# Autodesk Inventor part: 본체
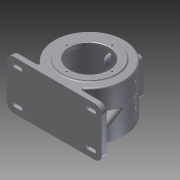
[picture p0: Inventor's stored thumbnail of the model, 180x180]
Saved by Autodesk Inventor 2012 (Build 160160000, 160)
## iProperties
Created: 2015-06
Part Number: 본체
Material: Default
Document SubType Name: Modeling
Designer: user
Density: 1 g/cm^3
Author: user
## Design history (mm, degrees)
sketch "스케치1"
  geometry: L1 (-115, 59)-(115, 59); L2 (115, 59)-(115, -59); L3 (115, -59)-(-115, -59); L4 (-115, -59)-(-115, 59); 3 further points
  constraints: 8 end point, 2 midpoint, 2 parallel, 1 horizontal, 1 horizontal alignment, 1 perpendicular, 1 vertical alignment
  dimensions: "d0" = 230 distance of L1.start L1.end; "d1" = 118 distance of L1.end L2.end
extrude "돌출1" new body sketch "스케치1" distance "d2" = 14; taper "d3" = 0 deg
node "작업 평면1"
sketch "스케치2"
  geometry: C1 r 65 at (115, 85); 1 further point
  constraints: 1 centre point, 1 vertical alignment
  dimensions: "d5" = 130 diameter of C1; "d6" = 85 distance of point (115, 0) C1.centre
extrude "돌출2" join sketch "스케치2" distance "d7" = 13; taper "d8" = 0 deg
sketch "스케치3"
  geometry: C1 r 65 at (0, 0) reference; C2 r 85 at (0, 0); 1 further point
  constraints: 1 centre point, 1 coincident
  dimensions: "d9" = 170 diameter of C2
extrude "돌출3" join sketch "스케치3" distance "d10" = 118; taper "d11" = 0 deg
sketch "스케치4"
  geometry: C1 r 65 at (115, 85); A1 r 85 centre (115, 85) between (161.733, 14) and (68.267, 14) reference; 1 further point
  constraints: 1 centre point, 1 coincident
  dimensions: "d12" = 130 diameter of C1
extrude "돌출4" join sketch "스케치4" distance "d13" = 3; taper "d14" = 0 deg
sketch "스케치5"
  geometry: C1 r 65 at (0, 0) reference; C2 r 47.5 at (0, 0); 1 further point
  constraints: 1 centre point, 1 coincident
  dimensions: "d15" = 95 diameter of C2
extrude "돌출5" cut sketch "스케치5" distance "d16" = 11; taper "d17" = 0 deg
sketch "스케치7"
  geometry: L1 (132.5, 51)-(37.5, 51) reference; L2 (85, 51)-(85, -72); L3 (150, -72)-(20, -72) reference; L4 (14, 59)-(14, -59) reference; L5 (85, 51)-(162, 51); L6 (162, 51)-(162, -51); L7 (162, -51)-(116, -51); L8 (116, -51)-(114.368, -47.5); L9 (114.368, -47.5)-(85, -47.5); 1 further point
  constraints: 12 end point, 3 perpendicular, 2 midpoint, 2 point on line
  dimensions: "d19" = 154 diameter of L5.end L2; "d20" = 102 distance of L5.end L6.end; "d21" = 62 diameter of L7.end L2; "d22" = 3.5 vertical distance of L7.end L8.end; "d23" = 115 deg angle of L7 L8
revolve "회전1" sketch "스케치7" stored, may be unused: angle "d24" = 90 deg
sketch "스케치8"
  geometry: C1 r 29.368 at (0, 0) reference; C2 r 23.5 at (0, 0); 1 further point
  constraints: 1 centre point, 1 coincident
  dimensions: "d25" = 47 diameter of C2
extrude "돌출6" cut sketch "스케치8" distance "d26" = 14; taper "d27" = 0 deg
sketch "스케치9"
  geometry: C1 r 23.5 at (0, 0) reference; C2 r 15 at (0, 0); 1 further point
  constraints: 1 centre point, 1 coincident
  dimensions: "d28" = 30 diameter of C2
extrude "돌출7" cut sketch "스케치9" distance "d29" = 3; taper "d30" = 0 deg
sketch "스케치11"
  geometry: L1 (-115, 59)-(115, 59) reference; L2 (0, 59)-(0, -59); L3 (-115, -59)-(-115, 59) reference; L4 (-115, 0)-(115, 0); L5 (115, 59)-(115, -59) reference; L6 (-97, 50)-(-81, 50); L7 (-97, 32)-(-81, 32); L8 (-97, -50)-(-81, -50); L9 (-97, -32)-(-81, -32); A1 r 9 centre (-97, 41) between (-97, 50) and (-97, 32); A2 r 9 centre (-81, 41) between (-81, 32) and (-81, 50); A3 r 9 centre (-97, -41) between (-97, -32) and (-97, -50); A4 r 9 centre (-81, -41) between (-81, -50) and (-81, -32); 3 further points
  constraints: 12 end point, 8 point on circle, 6 symmetric about line, 5 midpoint, 4 centre point, 4 coincident, 3 perpendicular, 3 tangent, 1 parallel, 2 other
  dimensions: "d40" = 18 diameter of A1; "d41" = 18 diameter of A2; "d42" = 16 distance of A2.centre A1.centre; "d43" = 194 diameter of A1.centre L2; "d44" = 82 diameter of A1.centre L4
extrude "돌출9" join sketch "스케치11" distance "d45" = 3; taper "d46" = 0 deg
sketch "스케치13"
  geometry: L1 (-97, 45)-(-81, 45); L2 (-97, 37)-(-81, 37); A1 r 9 centre (-97, 41) between (-97, 50) and (-97, 32) reference; A2 r 9 centre (-81, 41) between (-81, 32) and (-81, 50) reference; A3 r 4 centre (-97, 41) between (-97, 45) and (-97, 37); A4 r 4 centre (-81, 41) between (-81, 37) and (-81, 45); 1 further point
  constraints: 4 end point, 4 point on circle, 3 tangent, 2 centre point, 2 coincident, 1 parallel
  dimensions: "d47" = 8 diameter of A3; "d48" = 8 diameter of A4
extrude "돌출10" cut sketch "스케치13" stored distance "d49" = 3; taper "d50" = 0 deg
sketch "스케치14"
  geometry: L1 (-115, 14)-(-46.733, 14) reference; L2 (-109, 14)-(-84.87, 80.297); L3 (-109, 14)-(-46.733, 14); A1 r 85 centre (0, 85) between (46.733, 14) and (-46.733, 14) reference; 1 further point
  constraints: 4 end point, 1 collinear, 1 point on circle, 1 point on line
  dimensions: "d52" = 110 deg angle of L1 L2; "d53" = 6 distance of L2.start L1.start
extrude "돌출11" join sketch "스케치14" stored distance "d54" = 15; taper "d55" = 0 deg
node "작업 평면2"
sketch "스케치15"
  geometry: L1 (-42.5, 42.5)-(42.5, 42.5); L2 (42.5, 42.5)-(42.5, -42.5); L3 (42.5, -42.5)-(-42.5, -42.5); L4 (-42.5, -42.5)-(-42.5, 42.5); 3 further points
  constraints: 8 end point, 2 midpoint, 2 parallel, 2 perpendicular, 1 horizontal, 1 horizontal alignment, 1 vertical alignment
  dimensions: "d57" = 85 distance of L1.start L1.end
extrude "돌출12" join sketch "스케치15" stored distance "d58" = 15; taper "d59" = 0 deg
sketch "스케치16"
  geometry: C1 r 35 at (0, 0); 1 further point
  constraints: 1 centre point, 1 coincident
  dimensions: "d60" = 70 diameter of C1
extrude "돌출13" cut sketch "스케치16" stored distance "d61" = 15; taper "d62" = 0 deg
sketch "스케치18"
  geometry: C1 r 47.5 at (0, 0) reference; 2 further points
  constraints: 1 vertical alignment
  dimensions: "d64" = 55 distance of C1.centre point (0, 55)
hole "구멍1" sketch "스케치18" at (0, 55) diameter "d65" = 3.242; stored, may be unused: countersink angle "d69" = 90 deg, drill point angle "d71" = 0 deg; dims "d66" = 11, "d67" = 4, "d68" = 2, "d70" = 8
sketch "스케치19"
  geometry: L1 (42.5, -42.5)-(-42.5, -42.5) reference; L2 (42.5, 42.5)-(42.5, -42.5) reference; L3 (-42.5, 42.5)-(42.5, 42.5) reference; L4 (-42.5, -42.5)-(-42.5, 42.5) reference; L5 (-42.5, 0)-(42.5, 0); L6 (0, 42.5)-(0, -42.5); 1 further point
  constraints: 4 end point, 4 midpoint
  dimensions: "d75" = 71 diameter of point (-35.5, 35.5) L6; "d76" = 71 diameter of point (-35.5, 35.5) L5
hole "구멍2" sketch "스케치19" at (-35.5, 35.5) diameter "d77" = 3.242; stored, may be unused: countersink angle "d81" = 90 deg, drill point angle "d83" = 118 deg; dims "d78" = 10, "d79" = 4, "d80" = 2, "d82" = 13
fillet "모깎기2" dims "d85" = 7.5
fillet "모깎기3" dims "d86" = 7
fillet "모깎기4" dims "d87" = 3
fillet "모깎기5" dims "d88" = 3
fillet "모깎기7" dims "d90" = 18
fillet "모깎기9" dims "d92" = 3
fillet "모깎기10" dims "d93" = 3
fillet "모깎기11" dims "d94" = 3
chamfer "모따기1" distance "d95" = 1; stored, may be unused: second distance "d96" = 2, angle "d97" = 45 deg
chamfer "모따기2" distance "d98" = 1; stored, may be unused: second distance "d99" = 2, angle "d100" = 45 deg
chamfer "모따기3" distance "d101" = 1; stored, may be unused: second distance "d102" = 2, angle "d103" = 45 deg
node "작업 평면4"
  node "작업 평면3"
sketch "스케치20"
  geometry: 2 further points
  constraints: 1 horizontal alignment, 1 other
feature "엠보싱1" sketch "스케치20" dims "d104" = 0.5, "d105" = 0
fillet "모깎기13" dims "d107" = 3
fillet "모깎기14" dims "d108" = 3
fillet "모깎기15" dims "d109" = 0.3
fillet "모깎기16" dims "d110" = 3
fillet "모깎기17" dims "d111" = 3
node "솔리드1"
mirror "대칭1"
mirror "대칭2"
mirror "대칭3"
mirror "대칭4"
pattern_circular "원형 패턴1" dims angle "d73" = 360 deg
mirror "대칭5"
mirror "대칭6"
other parameters: "d4" = 13, "d56" = -173
